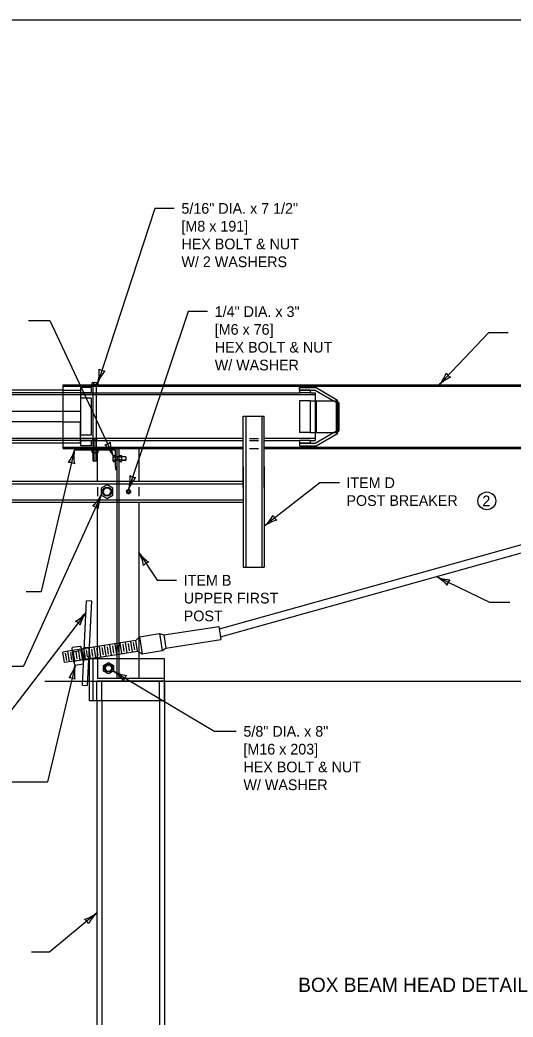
# Model space of a CAD drawing. Extents: x 49991.4 to 50021, y 49987.6 to 50011.4.
# Drawn here: x 50002.38 to 50005.14, y 49993.4 to 49999 of the extents above; entities that cross this region are included whole.
import ezdxf

# ---------------------------------------------------------------- set-up
doc = ezdxf.new("R2010")
doc.units = 0
for name, color, linetype in [('Level 1', 7, 'Continuous'), ('Level 2', 7, 'Continuous'), ('Level 3', 7, 'Continuous'), ('Level 4', 7, 'Continuous'), ('Level 63', 7, 'Continuous')]:
    doc.layers.add(name, color=color, linetype=linetype)

# ---------------------------------------------------------------- blocks, each defined once
blk = doc.blocks.new('HEX_NU')
at = {"layer": 'Level 63'}
for p, q in [((0, -0.325), (0, 0.325)), ((0.03, 0.433), (0.418, 0.433)), ((0.03, 0.216), (0.418, 0.216)), ((0.448, 0.325), (0.448, -0.325)), ((0.03, -0.216), (0.418, -0.216)), ((0.418, -0.433), (0.03, -0.433))]:
    blk.add_line(p, q, dxfattribs=at)
for centre, radius, start, end in [((0.21, 0.325), 0.21, 149.0201, 210.9799), ((0.796, 0), 0.796, 164.2217, 195.7782), ((0.238, 0.325), 0.21, 329.0201, 30.9799), ((-0.348, 0), 0.796, 344.2218, 15.7783), ((0.21, -0.325), 0.21, 149.0201, 210.9799), ((0.238, -0.325), 0.21, 329.0201, 30.9799)]:
    blk.add_arc(centre, radius, start, end, dxfattribs=at)
blk = doc.blocks.new('HEX_BO')
at = {"layer": 'Level 63'}
blk.add_lwpolyline([(0, 0.433), (-0.375, 0.2165), (-0.375, -0.2165), (0, -0.433), (0.375, -0.2165), (0.375, 0.2165)], close=True, dxfattribs=at)
blk.add_circle((0, 0), 0.25, dxfattribs=at)
for start, end in [(167.0572, 187.9055), (127.03, 148.675), (91.36985, 104.7376), (62.329189, 72.366658), (18.86795, 41.261061), (207.6209, 226.5812), (247.4266, 272.6797), (298.2529, 323.1939), (337.4806, 357.0806)]:
    blk.add_arc((0, 0), 0.2226, start, end, dxfattribs=at)

msp = doc.modelspace()

# ---------------------------------------------------------------- linework, layer by layer
at = {"layer": 'Level 1'}
for p, q in [((50002.7863, 49996.9625), (50002.8104, 49996.9625)), ((50002.6202, 49996.9193), (50002.1831, 49996.9193)), ((50002.6202, 49996.949), (50007.7121, 49996.949)), ((50002.6202, 49996.9193), (50002.6202, 49996.949)), ((50002.6202, 49996.9471), (50002.635, 49996.9471)), ((50002.6202, 49996.6222), (50002.6202, 49996.9193)), ((50002.635, 49996.9471), (50002.635, 49996.949)), ((50002.7903, 49996.9612), (50002.7903, 49996.949)), ((50002.8064, 49996.9612), (50002.8064, 49996.949)), ((50002.6202, 49996.8005), (50002.1831, 49996.8005)), ((50002.6202, 49996.7411), (50002.1831, 49996.7411)), ((50003.6301, 49996.3725), (50003.6301, 49996.7734)), ((50003.6301, 49996.7734), (50003.7489, 49996.7734)), ((50003.7489, 49996.3725), (50003.7489, 49996.7734)), ((50002.6202, 49996.6222), (50002.1831, 49996.6222)), ((50002.6202, 49996.5925), (50002.6202, 49996.6222)), ((50002.6202, 49996.5944), (50002.635, 49996.5944)), ((50002.6202, 49996.5925), (50003.6301, 49996.5925)), ((50002.635, 49996.5944), (50002.635, 49996.5925)), ((50002.6836, 49996.5925), (50002.6836, 49996.5846)), ((50002.6836, 49996.5846), (50002.8104, 49996.5846)), ((50002.7823, 49996.569), (50002.7823, 49996.5834)), ((50002.7863, 49996.5846), (50002.8104, 49996.5846)), ((50002.8077, 49996.5925), (50002.7891, 49996.5925)), ((50002.7903, 49996.569), (50002.7903, 49996.5834)), ((50002.8064, 49996.569), (50002.8064, 49996.5834)), ((50002.8123, 49996.4088), (50002.8123, 49996.5925)), ((50002.8145, 49996.5834), (50002.8145, 49996.569)), ((50003.044, 49996.5925), (50003.044, 49996.4088)), ((50003.7489, 49996.5925), (50007.7121, 49996.5925)), ((50002.8104, 49996.5679), (50002.7863, 49996.5679)), ((50002.7891, 49996.5239), (50002.7891, 49996.5684)), ((50002.7891, 49996.5239), (50002.791, 49996.522)), ((50002.8058, 49996.522), (50002.791, 49996.522)), ((50002.8077, 49996.5239), (50002.8058, 49996.522)), ((50002.8077, 49996.5684), (50002.8077, 49996.5239)), ((50002.8995, 49996.5479), (50002.8995, 49996.5238)), ((50002.9008, 49996.5439), (50002.913, 49996.5439)), ((50002.9008, 49996.5278), (50002.913, 49996.5278)), ((50002.9331, 49996.5479), (50002.9331, 49996.5238)), ((50002.9486, 49996.5519), (50002.9342, 49996.5519)), ((50002.9486, 49996.5439), (50002.9342, 49996.5439)), ((50002.9486, 49996.5278), (50002.9342, 49996.5278)), ((50002.9342, 49996.5198), (50002.9486, 49996.5198)), ((50002.9707, 49996.5451), (50002.9492, 49996.5451)), ((50002.9492, 49996.5265), (50002.9707, 49996.5265)), ((50002.9497, 49996.5238), (50002.9497, 49996.5479)), ((50002.9707, 49996.5451), (50002.9497, 49996.5451)), ((50002.9707, 49996.5265), (50002.9537, 49996.5265)), ((50002.9707, 49996.5451), (50002.9726, 49996.5433)), ((50002.9707, 49996.5451), (50002.9707, 49996.5265)), ((50002.9707, 49996.5265), (50002.9726, 49996.5284)), ((50002.9708, 49996.5433), (50002.9726, 49996.5433)), ((50002.9726, 49996.5284), (50002.9708, 49996.5284)), ((50002.9726, 49996.5284), (50002.9726, 49996.5433)), ((50003.6301, 49996.4913), (50003.6301, 49995.9252)), ((50003.7489, 49996.4913), (50003.7489, 49995.9252)), ((50001.5508, 49996.4088), (50003.6301, 49996.4088)), ((50006.292, 49996.3586), (50003.4954, 49995.5783)), ((50001.5508, 49996.2899), (50003.6301, 49996.2899)), ((50002.8123, 49995.4118), (50002.8123, 49996.2899)), ((50003.044, 49996.2899), (50003.044, 49995.4118)), ((50003.5023, 49995.5343), (50006.3005, 49996.3149)), ((50003.6301, 49995.9252), (50003.7489, 49995.9252)), ((50002.7276, 49995.2625), (50002.7513, 49995.7372)), ((50002.781, 49995.7357), (50002.7513, 49995.7372)), ((50002.7573, 49995.2611), (50002.781, 49995.7357)), ((50003.185, 49995.545), (50003.4931, 49995.593)), ((50003.4931, 49995.593), (50003.5046, 49995.5196)), ((50003.0475, 49995.5348), (50003.1612, 49995.5525)), ((50003.0475, 49995.5348), (50003.0624, 49995.4394)), ((50003.1612, 49995.5525), (50003.185, 49995.545)), ((50003.1612, 49995.5525), (50003.1761, 49995.4572)), ((50003.185, 49995.545), (50003.1964, 49995.4716)), ((50003.1964, 49995.4716), (50003.5046, 49995.5196)), ((50002.6701, 49995.4572), (50002.6175, 49995.449)), ((50002.656, 49995.3949), (50002.6468, 49995.4536)), ((50002.7379, 49995.4678), (50002.7222, 49995.4653)), ((50002.7371, 49995.4528), (50002.7349, 49995.4673)), ((50002.7734, 49995.4132), (50002.7669, 49995.4544)), ((50002.8123, 49995.4794), (50002.7678, 49995.4724)), ((50002.7867, 49995.4243), (50002.7803, 49995.4653)), ((50002.8027, 49995.4177), (50002.7936, 49995.4764)), ((50002.8123, 49995.4524), (50002.8096, 49995.4699)), ((50003.044, 49995.4504), (50003.0624, 49995.4394)), ((50003.0624, 49995.4394), (50003.1761, 49995.4572)), ((50003.1761, 49995.4572), (50003.1964, 49995.4716)), ((50002.6266, 49995.3903), (50002.6175, 49995.449)), ((50002.6792, 49995.3985), (50002.6266, 49995.3903)), ((50002.6399, 49995.4014), (50002.6335, 49995.4425)), ((50002.6693, 49995.406), (50002.6629, 49995.447)), ((50002.8123, 49995.4192), (50002.7648, 49995.4118)), ((50003.1884, 49995.4118), (50002.7648, 49995.4118)), ((50002.7648, 49995.4118), (50002.7648, 49995.1742)), ((50002.8123, 49995.4118), (50002.8123, 49995.3004)), ((50003.1884, 49995.1742), (50003.1884, 49995.4118)), ((50002.5165, 49995.2856), (50007.7121, 49995.2856)), ((50003.1884, 49995.2856), (50002.8094, 49995.2856)), ((50003.1884, 49995.3004), (50002.8123, 49995.3004)), ((50003.1884, 49995.2856), (50003.1884, 49992.8668)), ((50002.7276, 49995.2625), (50002.7573, 49995.2611)), ((50003.1884, 49995.1742), (50002.7648, 49995.1742)), ((50002.8094, 49995.1742), (50002.8094, 49992.8668)), ((50002.8364, 49995.1742), (50002.8364, 49992.8668)), ((50003.1614, 49995.1742), (50003.1614, 49992.8668))]:
    msp.add_line(p, q, dxfattribs=at)
msp.add_lwpolyline([(49999.3835, 49998.9992), (50016.7501, 49998.9992), (50016.7501, 49987.7988), (49999.3835, 49987.7988)], close=True, dxfattribs=at)
for points in [[(50002.8145, 49996.9612), (50002.8145, 49996.949), (50002.7823, 49996.949), (50002.7823, 49996.9612)], [(50002.9008, 49996.5198), (50002.913, 49996.5198), (50002.913, 49996.5519), (50002.9008, 49996.5519)]]:
    msp.add_lwpolyline(points, dxfattribs=at)
for centre, radius, start, end in [((50002.7863, 49996.9556), 0.00687, 54.1654, 125.8346), ((50002.7984, 49996.937), 0.0255, 71.6338, 108.3662), ((50002.8104, 49996.9556), 0.00687, 54.1844, 125.8534), ((50002.7863, 49996.5767), 0.00781, 59.0201, 120.9799), ((50002.7984, 49996.555), 0.0296, 74.2218, 105.7783), ((50002.8104, 49996.5767), 0.00781, 90.2015, 120.9799), ((50002.8104, 49996.5767), 0.00781, 59.0201, 90.3133), ((50002.7863, 49996.5757), 0.00781, 239.0201, 300.9799), ((50002.7984, 49996.5975), 0.0296, 254.2217, 285.7782), ((50002.8104, 49996.5757), 0.00781, 239.0201, 269.7985), ((50002.8104, 49996.5757), 0.00781, 269.6867, 300.9799), ((50002.9064, 49996.5479), 0.00686, 144.1545, 215.8237), ((50002.925, 49996.5358), 0.0255, 161.6338, 198.3662), ((50002.9064, 49996.5238), 0.00687, 144.1655, 215.8345), ((50002.9409, 49996.5479), 0.00781, 149.0201, 210.9799), ((50002.9626, 49996.5358), 0.0296, 164.2218, 195.7782), ((50002.9409, 49996.5238), 0.00781, 149.0201, 179.7985), ((50002.9409, 49996.5238), 0.00781, 179.6867, 210.9799), ((50002.9419, 49996.5479), 0.00781, 329.0201, 30.9799), ((50002.9201, 49996.5358), 0.0296, 344.2218, 15.7783), ((50002.9419, 49996.5238), 0.00781, 0.2015, 30.9799), ((50002.9419, 49996.5238), 0.00781, 329.0201, 0.3133)]:
    msp.add_arc(centre, radius, start, end, dxfattribs=at)
at = {"layer": 'Level 2'}
msp.add_circle((50004.9978, 49996.298), 0.05, dxfattribs=at)
at = {"layer": 'Level 3'}
for p, q in [((50003.1335, 49997.9408), (50002.8145, 49996.9612)), ((50003.2436, 49997.9408), (50003.1335, 49997.9408)), ((50003.3206, 49997.3609), (50002.9869, 49996.3627)), ((50003.4306, 49997.3609), (50003.3206, 49997.3609)), ((50002.4244, 49997.312), (50002.5444, 49997.312)), ((50002.5444, 49997.312), (50002.9008, 49996.5519)), ((50005.0067, 49997.2421), (50004.7304, 49996.949)), ((50005.1167, 49997.2421), (50005.0067, 49997.2421)), ((50002.6836, 49996.5846), (50002.4972, 49995.7892)), ((50004.06, 49996.3998), (50003.7489, 49996.1564)), ((50004.17, 49996.3998), (50004.06, 49996.3998)), ((50002.8325, 49996.3305), (50002.3974, 49995.3703)), ((50003.044, 49996.0087), (50003.1466, 49995.852)), ((50003.1466, 49995.852), (50003.2566, 49995.852)), ((50004.7147, 49995.8725), (50005.0165, 49995.7276)), ((50002.4123, 49995.7892), (50002.4972, 49995.7892)), ((50005.1266, 49995.7276), (50005.0165, 49995.7276)), ((50002.7481, 49995.6717), (50002.2871, 49995.0685)), ((50002.2905, 49995.3703), (50002.3974, 49995.3703)), ((50002.6869, 49995.3739), (50002.5314, 49994.7204)), ((50002.9021, 49995.3419), (50003.4717, 49995.0036)), ((50003.5917, 49995.0036), (50003.4717, 49995.0036)), ((50001.9905, 49994.7204), (50002.5314, 49994.7204)), ((50002.8094, 49993.9837), (50002.5445, 49993.7648)), ((50002.4423, 49993.7648), (50002.5445, 49993.7648))]:
    msp.add_line(p, q, dxfattribs=at)
for centre, radius, start, end in [((50002.5896, 49997.0223), 0.233, 344.7878, 4.0377), ((50003.0228, 49996.8837), 0.2223, 139.4165, 159.6), ((50002.8542, 49997.0831), 0.0548, 234.0993, 269.8217), ((50004.5532, 49997.1002), 0.233, 319.5182, 338.7681), ((50004.8857, 49996.79), 0.2223, 114.1469, 134.3304), ((50004.8183, 49997.0423), 0.0548, 208.8297, 244.5521), ((50002.8464, 49996.668), 0.0548, 277.2626, 312.9849), ((50003.1058, 49996.6379), 0.2223, 182.5798, 202.7633), ((50002.4694, 49996.6441), 0.2223, 324.2721, 344.4556), ((50002.9128, 49996.5427), 0.233, 169.6434, 188.8932), ((50002.695, 49996.4427), 0.233, 27.9511, 47.2009), ((50002.6543, 49996.4597), 0.0548, 58.9549, 94.6772), ((50002.7626, 49996.4256), 0.233, 344.3397, 3.5896), ((50003.1947, 49996.2836), 0.2223, 138.9684, 159.1519), ((50003.0276, 49996.4843), 0.0548, 233.6512, 269.3736), ((50002.634, 49996.4306), 0.2223, 313.0796, 333.2632), ((50003.0492, 49996.245), 0.233, 158.4509, 177.7008), ((50002.7796, 49996.2137), 0.0548, 47.7625, 83.4848), ((50003.5964, 49996.3326), 0.233, 310.8713, 330.1212), ((50003.8786, 49995.9758), 0.2223, 105.5, 125.6835), ((50003.8499, 49996.2354), 0.0548, 200.1828, 235.9052), ((50002.8531, 49995.8948), 0.2223, 10.6401, 30.8236), ((50003.2325, 49996.1457), 0.233, 216.0114, 235.2612), ((50003.1142, 49995.9014), 0.0548, 105.3229, 141.0452), ((50004.6103, 49995.6762), 0.2223, 41.8155, 61.999), ((50004.805, 49996.0873), 0.233, 247.1868, 266.4366), ((50004.8303, 49995.817), 0.0548, 136.4983, 172.2206), ((50002.5771, 49995.8139), 0.2223, 300.0675, 320.251), ((50002.6702, 49995.5699), 0.0548, 34.7503, 70.4726), ((50002.9399, 49995.5396), 0.233, 145.4388, 164.6886), ((50002.4729, 49995.4343), 0.2223, 324.0767, 344.2602), ((50002.9159, 49995.3313), 0.233, 169.448, 188.6978), ((50002.7809, 49995.1555), 0.2223, 36.7981, 56.9816), ((50003.0109, 49995.548), 0.233, 242.1694, 261.4193), ((50002.6572, 49995.2492), 0.0548, 58.7595, 94.4819), ((50003.0124, 49995.2766), 0.0548, 131.4809, 167.2033), ((50002.6749, 49994.1608), 0.2223, 287.0241, 307.2076), ((50002.7105, 49993.9021), 0.0548, 21.7069, 57.4293), ((50002.9665, 49993.8117), 0.233, 132.3954, 151.6452)]:
    msp.add_arc(centre, radius, start, end, dxfattribs=at)
at = {"layer": 'Level 4'}
for p, q in [((50002.6202, 49996.9416), (50007.7121, 49996.9416)), ((50002.6202, 49996.9193), (50002.7178, 49996.9193)), ((50002.635, 49996.9471), (50002.6406, 49996.9416)), ((50002.7772, 49996.9341), (50002.7178, 49996.9341)), ((50002.7178, 49996.9341), (50002.7178, 49996.9044)), ((50002.7178, 49996.9193), (50002.7178, 49996.8005)), ((50002.7772, 49996.9341), (50002.7772, 49996.9044)), ((50002.7872, 49996.9416), (50002.7872, 49996.949)), ((50002.7891, 49996.5684), (50002.7891, 49996.949)), ((50002.8077, 49996.5684), (50002.8077, 49996.949)), ((50002.8095, 49996.9416), (50002.8095, 49996.949)), ((50003.9459, 49996.9341), (50004.039, 49996.9341)), ((50003.9459, 49996.9193), (50003.9459, 49996.9341)), ((50003.9459, 49996.9193), (50004.0351, 49996.9193)), ((50004.0054, 49996.9193), (50003.9459, 49996.9193)), ((50003.9459, 49996.9193), (50003.9459, 49996.9044)), ((50004.0054, 49996.9193), (50004.0054, 49996.9044)), ((50004.0351, 49996.9193), (50004.1379, 49996.8599)), ((50004.039, 49996.9341), (50004.1602, 49996.8642)), ((50004.0351, 49996.8933), (50001.3023, 49996.8933)), ((50002.7178, 49996.9044), (50002.1831, 49996.9044)), ((50002.7178, 49996.9044), (50003.9459, 49996.9044)), ((50002.7772, 49996.9044), (50002.7178, 49996.9044)), ((50002.7178, 49996.8747), (50002.7178, 49996.6668)), ((50002.7772, 49996.8747), (50002.7178, 49996.8747)), ((50002.7772, 49996.8747), (50002.7772, 49996.6668)), ((50002.7872, 49996.8933), (50002.7872, 49996.9044)), ((50002.8095, 49996.8933), (50002.8095, 49996.9044)), ((50004.0054, 49996.9044), (50003.9459, 49996.9044)), ((50003.9459, 49996.8599), (50003.9459, 49996.6817)), ((50004.0054, 49996.8599), (50003.9459, 49996.8599)), ((50004.0054, 49996.9044), (50004.0351, 49996.9044)), ((50004.0054, 49996.8599), (50004.0054, 49996.6817)), ((50004.0054, 49996.8599), (50004.1602, 49996.8599)), ((50004.0351, 49996.9044), (50004.0351, 49996.8599)), ((50004.0351, 49996.8599), (50004.0351, 49996.6817)), ((50004.039, 49996.8599), (50004.039, 49996.6817)), ((50004.1528, 49996.8513), (50004.1379, 49996.8599)), ((50004.1528, 49996.8599), (50004.1528, 49996.6817)), ((50004.1528, 49996.8513), (50004.1578, 49996.8599)), ((50004.1528, 49996.8513), (50004.1602, 49996.8513)), ((50004.1528, 49996.8513), (50004.1528, 49996.6902)), ((50004.1578, 49996.8599), (50004.1602, 49996.8642)), ((50004.1602, 49996.8599), (50004.1602, 49996.6817)), ((50004.1602, 49996.8513), (50004.1677, 49996.8513)), ((50004.1677, 49996.8513), (50004.1677, 49996.6902)), ((50002.7178, 49996.8005), (50002.6202, 49996.8005)), ((50002.6202, 49996.7411), (50002.7178, 49996.7411)), ((50002.7178, 49996.6222), (50002.7178, 49996.7411)), ((50003.6449, 49996.7734), (50003.6449, 49995.9252)), ((50003.734, 49996.7734), (50003.734, 49995.9252)), ((50004.0054, 49996.6817), (50003.9459, 49996.6817)), ((50004.0054, 49996.6817), (50004.1602, 49996.6817)), ((50004.0351, 49996.6817), (50004.0351, 49996.6371)), ((50004.0351, 49996.6222), (50004.1379, 49996.6817)), ((50004.1379, 49996.6817), (50004.1528, 49996.6902)), ((50004.1528, 49996.6902), (50004.1578, 49996.6817)), ((50004.1528, 49996.6902), (50004.1602, 49996.6902)), ((50004.1578, 49996.6817), (50004.1602, 49996.6774)), ((50004.1602, 49996.6902), (50004.1677, 49996.6902)), ((50003.6301, 49996.6482), (50001.3023, 49996.6482)), ((50002.7178, 49996.6371), (50002.1831, 49996.6371)), ((50002.7772, 49996.6668), (50002.7178, 49996.6668)), ((50002.7178, 49996.6371), (50002.7178, 49996.6074)), ((50002.7772, 49996.6371), (50002.7178, 49996.6371)), ((50002.7178, 49996.6371), (50003.6301, 49996.6371)), ((50002.7772, 49996.6371), (50002.7772, 49996.6074)), ((50002.7872, 49996.6371), (50002.7872, 49996.6482)), ((50002.8077, 49996.6462), (50002.7891, 49996.6462)), ((50002.791, 49996.6462), (50002.791, 49996.5679)), ((50002.8058, 49996.5679), (50002.8058, 49996.6462)), ((50002.8095, 49996.6371), (50002.8095, 49996.6482)), ((50003.6652, 49996.6482), (50003.7157, 49996.6482)), ((50003.6652, 49996.6371), (50003.7157, 49996.6371)), ((50004.0351, 49996.6482), (50003.7489, 49996.6482)), ((50003.7489, 49996.6371), (50003.9459, 49996.6371)), ((50004.0054, 49996.6371), (50003.9459, 49996.6371)), ((50003.9459, 49996.6371), (50003.9459, 49996.6222)), ((50004.0054, 49996.6371), (50004.0351, 49996.6371)), ((50004.0054, 49996.6371), (50004.0054, 49996.6222)), ((50004.039, 49996.6074), (50004.1602, 49996.6774)), ((50002.7178, 49996.6222), (50002.6202, 49996.6222)), ((50002.6202, 49996.6), (50003.6301, 49996.6)), ((50002.635, 49996.5944), (50002.6406, 49996.6)), ((50002.7772, 49996.6074), (50002.7178, 49996.6074)), ((50002.7872, 49996.6), (50002.7872, 49996.5925)), ((50002.8095, 49996.6), (50002.8095, 49996.5925)), ((50002.8104, 49996.5846), (50002.909, 49996.5846)), ((50002.9132, 49996.4913), (50002.9132, 49996.5804)), ((50002.9231, 49995.3004), (50002.9231, 49996.5925)), ((50002.9332, 49995.3004), (50002.9332, 49996.5925)), ((50003.6652, 49996.5925), (50003.7157, 49996.5925)), ((50003.7489, 49996.6), (50007.7121, 49996.6)), ((50003.9459, 49996.6222), (50004.0351, 49996.6222)), ((50004.0054, 49996.6222), (50003.9459, 49996.6222)), ((50003.9459, 49996.6222), (50003.9459, 49996.6074)), ((50003.9459, 49996.6074), (50004.039, 49996.6074)), ((50002.7891, 49996.5239), (50002.8077, 49996.5239)), ((50002.791, 49996.5679), (50002.791, 49996.5239)), ((50002.8058, 49996.5239), (50002.8058, 49996.5679)), ((50002.9205, 49996.547), (50002.913, 49996.547)), ((50002.9497, 49996.5451), (50002.913, 49996.5451)), ((50002.9497, 49996.5265), (50002.913, 49996.5265)), ((50002.9205, 49996.5247), (50002.913, 49996.5247)), ((50002.9251, 49996.5265), (50002.9251, 49996.5451)), ((50002.9299, 49996.547), (50002.9373, 49996.547)), ((50002.9299, 49996.5247), (50002.9373, 49996.5247)), ((50002.9132, 49996.4913), (50002.9132, 49996.4737)), ((50002.9132, 49996.4737), (50002.9231, 49996.4737)), ((50001.5508, 49996.3939), (50003.6301, 49996.3939)), ((50002.8123, 49996.3743), (50002.8123, 49996.3243)), ((50003.044, 49996.3743), (50003.044, 49996.3243)), ((50001.5508, 49996.3048), (50003.6301, 49996.3048)), ((50003.0284, 49995.513), (50002.8123, 49995.4794)), ((50003.0082, 49995.4498), (50002.999, 49995.5085)), ((50003.044, 49995.5309), (50003.0284, 49995.513)), ((50003.0375, 49995.4543), (50003.0284, 49995.513)), ((50002.7222, 49995.4653), (50002.6701, 49995.4572)), ((50002.6853, 49995.3994), (50002.6762, 49995.4581)), ((50002.6986, 49995.4105), (50002.6922, 49995.4516)), ((50002.7147, 49995.404), (50002.7055, 49995.4627)), ((50002.728, 49995.4151), (50002.7216, 49995.4562)), ((50002.7371, 49995.4528), (50002.744, 49995.4086)), ((50002.7678, 49995.4724), (50002.7379, 49995.4678)), ((50002.7678, 49995.4724), (50002.7382, 49995.4739)), ((50002.7573, 49995.4197), (50002.7509, 49995.4608)), ((50002.7669, 49995.4544), (50002.7642, 49995.4719)), ((50002.8123, 49995.4192), (50003.0375, 49995.4543)), ((50002.816, 49995.4288), (50002.8123, 49995.4524)), ((50002.8321, 49995.4223), (50002.8229, 49995.481)), ((50002.8454, 49995.4334), (50002.839, 49995.4745)), ((50002.8614, 49995.4269), (50002.8523, 49995.4856)), ((50002.8747, 49995.438), (50002.8683, 49995.4791)), ((50002.8908, 49995.4315), (50002.8816, 49995.4902)), ((50002.9041, 49995.4426), (50002.8977, 49995.4836)), ((50002.9201, 49995.436), (50002.911, 49995.4947)), ((50002.9334, 49995.4471), (50002.927, 49995.4882)), ((50002.9495, 49995.4406), (50002.9403, 49995.4993)), ((50002.9628, 49995.4517), (50002.9564, 49995.4928)), ((50002.9788, 49995.4452), (50002.9697, 49995.5039)), ((50002.9921, 49995.4563), (50002.9857, 49995.4974)), ((50003.0215, 49995.4609), (50003.0151, 49995.5019)), ((50003.0375, 49995.4543), (50003.044, 49995.4504)), ((50002.6792, 49995.3985), (50002.7318, 49995.4067)), ((50002.7648, 49995.4118), (50002.7348, 49995.4072)), ((50002.7348, 49995.4072), (50002.7645, 49995.4057)), ((50002.7871, 49995.4118), (50002.7871, 49995.1742)), ((50003.044, 49995.4118), (50003.044, 49995.3004)), ((50002.8094, 49995.1742), (50002.8094, 49995.2856)), ((50002.8364, 49995.1742), (50002.8364, 49995.2856)), ((50003.1614, 49995.1742), (50003.1614, 49995.2856))]:
    msp.add_line(p, q, dxfattribs=at)
for centre, radius in [((50002.8659, 49996.3498), 0.026), ((50002.9869, 49996.3498), 0.0111), ((50002.8742, 49995.358), 0.0223)]:
    msp.add_circle(centre, radius, dxfattribs=at)
for centre, radius in [((50002.909, 49996.5804), 0.00416), ((50002.915, 49996.5846), 0.00799)]:
    msp.add_arc(centre, radius, 0, 90, dxfattribs=at)

# ---------------------------------------------------------------- block references
at = {"layer": 'Level 1'}
for p, xscale, yscale in [((50002.8659, 49996.3498), 0.08911032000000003, 0.08911032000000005), ((50002.9869, 49996.3498), 0.029703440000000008, 0.029703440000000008)]:
    msp.add_blockref('HEX_BO', p, dxfattribs=dict(at, xscale=xscale, yscale=yscale))
for name, p, xscale, yscale, rotation in [('HEX_NU', (50002.6754, 49995.4242), 0.1188137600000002, 0.11881376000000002, 8.859926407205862), ('HEX_BO', (50002.8742, 49995.358), 0.07426335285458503, -0.07426335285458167, 180)]:
    msp.add_blockref(name, p, dxfattribs=dict(at, xscale=xscale, yscale=yscale, rotation=rotation))

# ---------------------------------------------------------------- texts
at = {"layer": 'Level 2'}
for s, height, p in [('5/16" DIA. x 7 1/2" ', 0.06, (50003.2836, 49997.9108)), ('[M8 x 191]', 0.06, (50003.2836, 49997.8108)), ('HEX BOLT & NUT', 0.06, (50003.2836, 49997.7108)), ('W/ 2 WASHERS', 0.06, (50003.2836, 49997.6108)), ('1/4" DIA. x 3"', 0.06, (50003.4706, 49997.331)), ('[M6 x 76] ', 0.06, (50003.4706, 49997.231)), ('HEX BOLT & NUT ', 0.06, (50003.4706, 49997.131)), ('W/ WASHER', 0.06, (50003.4706, 49997.031)), ('ITEM D ', 0.06, (50004.21, 49996.3698)), ('POST BREAKER', 0.06, (50004.21, 49996.2698)), ('2', 0.06, (50004.9727, 49996.268)), ('ITEM B', 0.06, (50003.2966, 49995.8219)), ('UPPER FIRST', 0.06, (50003.2966, 49995.7219)), ('POST', 0.06, (50003.2966, 49995.6219)), ('5/8" DIA. x 8"', 0.06, (50003.6317, 49994.9736)), ('[M16 x 203]', 0.06, (50003.6317, 49994.8736)), ('HEX BOLT & NUT', 0.06, (50003.6317, 49994.7736)), ('W/ WASHER', 0.06, (50003.6317, 49994.6736)), ('BOX BEAM HEAD DETAIL', 0.08, (50003.9391, 49993.54))]:
    msp.add_text(s, height=height, dxfattribs=at).set_placement(p)

doc.saveas('drawing.dxf')
